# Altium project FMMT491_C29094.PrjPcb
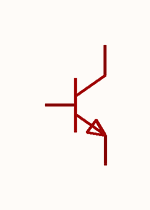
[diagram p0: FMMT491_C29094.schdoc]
1 sheet, 1 parts. Net scope: global (net labels, ports and power ports of the same name join across sheets).

## Sheet FMMT491_C29094.schdoc
size 127 x 101 mm

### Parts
Q?  fmmt491(range:100-300)  [SOT-23-3_L2.9-W1.3-P1.90-LS2.4-BR]  (value not drawn)

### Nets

Not connected (* = marked no-connect by the designer): Q? 1(B) 2(E) 3(C)

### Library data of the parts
Q? = fmmt491(range:100-300): 晶体管类型:NPN;集电极电流(Ic):1A;集射极击穿电压(Vceo):60V;耗散功率(Pd):250mW;直流电流增益(hFE):300;; Manufacturer: CJ(江苏长电/长晶); Symbol: FMMT491_C29094; AddInBom: yes; ModelId: c62791f0466c4ae2a892c056b845b0ca; ModelName: SOT-23-3P_L2.9-W1.3-H1.0-LS2.4-P0.95; ModelTransform: 98.425,114.173,0,180,0,0,0.0005,-0.0005,0; type: NPN; Current - Collector(Ic): 1A; Collector - Emitter Voltage VCEO: 60V; Pd - Power Dissipation: 250mW; DC Current Gain: 300; Transition frequency(fT): 150MHz; Current - Collector Cutoff: 100nA; Vce Saturation(VCE(sat)): 500mV; Emitter-Base Voltage(Vebo): 5V; Number: 1个NPN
